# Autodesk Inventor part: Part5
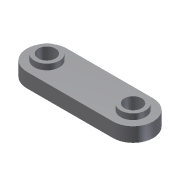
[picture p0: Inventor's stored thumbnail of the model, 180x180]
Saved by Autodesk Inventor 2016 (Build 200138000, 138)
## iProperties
Shininess: 77.0
Length Units: 11269
Angle Units: 11279
Time Units: 11290
Mass Units: 11283
Length Display Precision: 3
Angle Display Precision: 2
Created: 2002-01
Part Number: Part5
Document SubType Name: Modeling
Designer: ***
Density: 1 g/cm^3
Material: Generic
Appearance: Default
Density: 0.0
Volumn: 0.0
Area: 0.0
PropertySet Name: Model Information
Control State: 0
Master: False
Checked Out: False
Author: ***
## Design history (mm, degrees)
sketch "Sketch1"
  geometry: L1 (-33.118, 12.346)-(26.882, 12.361); L2 (-33.111, -15.654)-(26.889, -15.639); C1 r 6 at (-33.114, -1.654); C2 r 6 at (26.886, -1.639); A1 r 14 centre (-33.114, -1.654) between (-33.118, 12.346) and (-33.111, -15.654); A2 r 14 centre (26.886, -1.639) between (26.889, -15.639) and (26.882, 12.361)
  constraints: 4 centre point, 4 end point, 4 point on circle, 4 tangent, 2 coincident, 2 equal radius
  dimensions: "d0" = 60 distance of L1.start L1.end; "d1" = 14 radius of A1; "d2" = 12 diameter of C1
extrude "Extrusion1" new body sketch "Sketch1" distance "d3" = 10; taper "d4" = 0 deg
sketch "Sketch2"
  geometry: C1 r 6 at (26.886, -1.639) reference; C2 r 6 at (-33.114, -1.654) reference; C3 r 8.694 at (-33.114, -1.654); C4 r 8.694 at (26.886, -1.639)
  constraints: 2 centre point, 2 coincident, 1 equal radius
extrude "Extrusion2" join sketch "Sketch2" distance "d5" = 4; taper "d6" = 0 deg
body "Solid1"
